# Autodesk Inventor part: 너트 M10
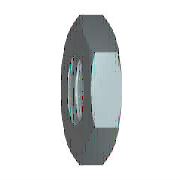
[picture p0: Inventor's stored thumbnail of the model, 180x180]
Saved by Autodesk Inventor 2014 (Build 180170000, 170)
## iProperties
IsCustomPart: 1
Created: 2012-02
Part Number: 너트 M10
Material: 강철, 연강
Description: 6각 가는 너트 - 이중 모따기
Document SubType Name: Modeling
Standard: JIS B 1181
Designer: mduedu
Standards Organization: JIS
Language: ko-KR
Size Designation: A/B M10
Categories: <MemberInstance><Categories><Category DisplayName="조임쇠" InternalName="e4da775c-781d-43d5-af7c-5136215cf5a6" Mnemonic="FSTN"><Category DisplayName="너트" InternalN
Density: 1 g/cm^3
Appearance: Orange
Author: mduedu
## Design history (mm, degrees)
sketch "스케치1"
  geometry: L1 (-9.238, 0)-(-4.619, 8); L2 (-4.619, 8)-(4.619, 8); L3 (4.619, 8)-(9.238, 0); L4 (9.238, 0)-(4.619, -8); L5 (4.619, -8)-(-4.619, -8); L6 (-4.619, -8)-(-9.238, 0); 2 further points
  constraints: 12 end point, 1 coincident, 1 horizontal, 11 other
  dimensions: "d0" = 18.47521 distance of L3.end L1.start (= 1.1547 x SW)
extrude "본체" new body sketch "스케치1" distance "d1" = 5 (= KOH); taper "d2" = 0 deg
sketch "스케치2"
  geometry: L1 (0, 4.619)-(0, 9.238) reference; L2 (0, 9.238)-(5, 9.238) reference; L3 (5, 4.619)-(5, 9.238) reference; L4 (-1, 0)-(6, 0) reference; L5 (0.715, 9.238)-(0, 8); L6 (4.285, 9.238)-(5, 8)
  constraints: 4 end point, 4 point on line
  dimensions: "d3" = 30 deg angle of L1 L5 (= ANG1); "d4" = 30 deg angle of L3 L6 (= ANG2); "d5" = 16 diameter of L5.end L4 (= SW0); "d6" = 16 diameter of L6.end L4 (= SW01)
revolve "모따기1" sketch "스케치2" stored, may be unused: angle "d7" = 90 deg
sketch "스케치3"
  geometry: A1 r 8 centre (0, 0) between (-4, -6.928) and (4, -6.928) reference; 1 further point
  constraints: 1 coincident
hole "스레드" sketch "스케치3" at (0, 0) diameter "d25" = 8.376; stored, may be unused: countersink angle "d29" = 82 deg, drill point angle "d31" = 118 deg; dims "d26" = 6, "d27" = 4, "d28" = 2, "d30" = 8
workaxis "Work Axis1"
workplane "Work Plane1"
body "Solid1"
chamfer "모따기2" distance "d8" = 0.8119 (= -0.5 x GD1 + 0.5 x NND); stored, may be unused: angle "d9" = 30 deg, second distance "d40" = 0.8119 (= -0.5 x GD1 + 0.5 x NND)
chamfer "모따기3" distance "d10" = 0.8119 (= -0.5 x GD1 + 0.5 x NND); stored, may be unused: angle "d11" = 30 deg, second distance "d41" = 0.8119 (= -0.5 x GD1 + 0.5 x NND)
other parameters: "ANG1" = 30 deg [user parameter; used in 1 equation term], "ANG2" = 30 deg [user parameter; used in 1 equation term], "KOH" = 5 [user parameter; used in 1 equation term], "SW" = 16 [user parameter; used in 4 equation terms], "SW0" = 16 (= SW) [user parameter; used in 1 equation term], "SW01" = 16 (= SW) [user parameter; used in 1 equation term], "GD1" = 8.3762 (computed from THREADDIA, PTC, TOA) [user parameter; used in 4 equation terms], "d13" = 0, "d14" = 0, "d39" = 0, "d42" = 0, "GUL" = 0.8119 (= 0.541266 x PTC) [user parameter], "TPU" = 6.66667 (computed from PTC) [user parameter], "TOA" = 30 deg [user parameter; used in 1 equation term], "PTC" = 1.5 [user parameter; used in 4 equation terms], "E0" = 18.48 (= 1.155 x SW) [user parameter], "GAL" = 0.8119 (= 0.541266 x PTC) [user parameter]
